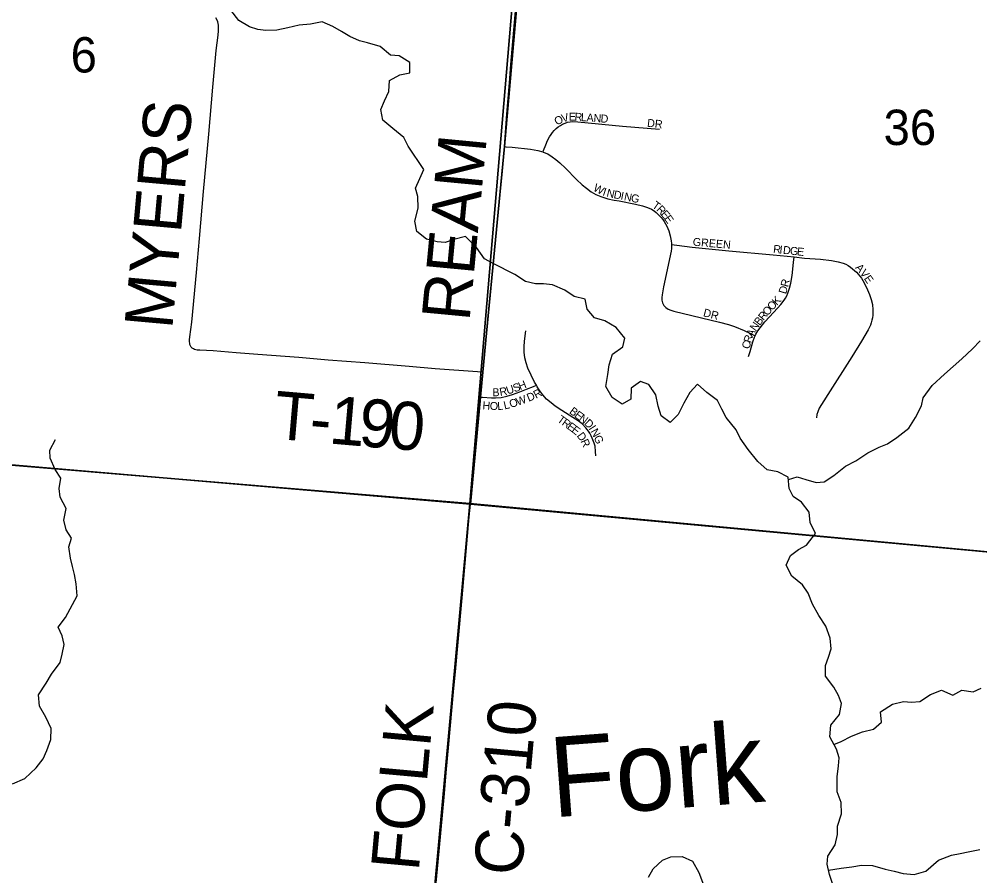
# Model space of a CAD drawing. Extents: x 1410790 to 1770854, y 566777 to 831614.
# Drawn here: x 1564816 to 1570818, y 709632 to 714986 of the extents above; entities that cross this region are included whole.
import ezdxf

# ---------------------------------------------------------------- set-up
doc = ezdxf.new("R2010")
doc.units = 0
for name, color, linetype in [('GM_X_County_Road', 7, 'Continuous'), ('GM_X_County_Road_Text', 7, 'Continuous'), ('GM_X_Minor_River', 7, 'Continuous'), ('GM_X_Minor_River_Text', 7, 'Continuous'), ('GM_X_Section', 7, 'Continuous'), ('GM_X_Section_Text', 7, 'Continuous'), ('GM_X_Township', 7, 'Continuous'), ('GM_X_Township_Road', 7, 'Continuous'), ('GM_X_Township_Road_Text', 7, 'Continuous'), ('GM_X_Township_Subdivision', 7, 'Continuous'), ('GM_X_Township_Subdivision_Text', 7, 'Continuous')]:
    doc.layers.add(name, color=color, linetype=linetype)

msp = doc.modelspace()

# ---------------------------------------------------------------- linework, layer by layer
at = {"layer": 'GM_X_County_Road'}
for points in [[(1567847.7, 714189.3), (1567863.9, 714392.9), (1567879.1, 714588.9), (1567888.8, 714703.3), (1567915.8, 715013.6), (1567937.6, 715258.5), (1567954, 715438.2), (1567971.6, 715634.2), (1567990.8, 715846.5), (1568008.1, 716042.5), (1568019.3, 716173.2), (1568035.4, 716352.9), (1568048.2, 716499.8), (1568060.7, 716646.9), (1568077.6, 716826.4), (1568091.6, 716973.3), (1568102.9, 717087.5), (1568116.8, 717250.8), (1568119.6, 717278.9)], [(1567744.9, 713110.3), (1567755.7, 713219.6), (1567769.2, 713366.2), (1567781.9, 713496.5), (1567791.5, 713594.4), (1567804.6, 713724.9), (1567835.3, 714034.1), (1567841.8, 714115.3), (1567847.7, 714189.3)], [(1567713.4, 712780.3), (1567736.3, 713023.8), (1567744.9, 713110.3)], [(1567699, 712623.5), (1567705.5, 712697.4), (1567713.4, 712780.3)], [(1567635.2, 711955.3), (1567671.1, 712328.1), (1567686.6, 712485.1), (1567699, 712623.5)], [(1567399.9, 709328.4), (1567405.5, 709411.7), (1567439.3, 709786.8), (1567473.1, 710145.6), (1567484.9, 710276.2), (1567501.2, 710455.7), (1567530.6, 710782), (1567544, 710928.8), (1567559.1, 711092), (1567583.2, 711369.5), (1567627.9, 711875.4), (1567635.1, 711954), (1567635.2, 711955.3)]]:
    msp.add_lwpolyline(points, dxfattribs=at)
at = {"layer": 'GM_X_Minor_River'}
for points in [[(1568475.7, 713100.2), (1568411.8, 713119.1), (1568364.3, 713173.8), (1568353.1, 713236.1), (1568283.1, 713253), (1568225.4, 713291.8), (1568147.6, 713324.8), (1568091.5, 713331.5), (1568041.4, 713332.1), (1567979.4, 713346.9), (1567913.7, 713389.8), (1567778.2, 713459.6), (1567724.4, 713488.3), (1567673.2, 713559.2), (1567605.8, 713628.2), (1567531.4, 713609), (1567477, 713589.6), (1567426.9, 713594.2), (1567361, 713611), (1567301.4, 713659.9), (1567288.2, 713724.3), (1567309.2, 713804.2), (1567306.1, 713878.5), (1567292.7, 713928.8), (1567319.6, 713990.7), (1567344.3, 714046.5), (1567245.9, 714192.1), (1567218.5, 714246.6), (1567151, 714301.6), (1567087.4, 714354.5), (1567076.2, 714420.8), (1567099, 714474.7), (1567125.8, 714534.5), (1567130.7, 714602.7), (1567195.3, 714638), (1567257.6, 714651.3), (1567256.4, 714715.5), (1567190.7, 714756.4), (1567136.6, 714761.1), (1567071.1, 714816), (1566993.2, 714839), (1566943.2, 714849.6), (1566881.4, 714878.5), (1566829.6, 714909.2), (1566775.8, 714939.9), (1566710, 714968.8), (1566635.7, 714955.6), (1566565.4, 714948.5), (1566495, 714931.3), (1566426.6, 714918), (1566356.4, 714914.9), (1566306.3, 714921.5), (1566254.4, 714938.2), (1566188.7, 714977.1), (1566139.3, 715041.8)], [(1569901.5, 709572.1), (1569878.3, 709640.6), (1569865.1, 709704.9), (1569869.7, 709755), (1569914.7, 709824.8), (1569929.6, 709890.8), (1569930.2, 709943), (1569953.3, 710018.9), (1569952.1, 710089.2), (1569926.9, 710157.7), (1569928.1, 710250), (1569935, 710320.2), (1569939.6, 710370.3), (1569922.2, 710422.7), (1569881.1, 710501.4), (1569888, 710573.5), (1569941, 710639.2), (1569953.9, 710709.2), (1569936.5, 710759.6), (1569907.1, 710810.1), (1569853.8, 710879), (1569854.6, 710947.2), (1569873.3, 710999.1), (1569890, 711051.1), (1569882.8, 711117.4), (1569855.7, 711191.9), (1569812.4, 711258.7), (1569773.2, 711329.4), (1569746, 711397.9), (1569710.5, 711450.5), (1569643, 711505.5), (1569607.8, 711574.1), (1569634.6, 711634), (1569685.2, 711671.5), (1569735.7, 711699), (1569792.8, 711770.5), (1569757.5, 711839.2), (1569752.4, 711905.5), (1569705, 711968.2), (1569653.3, 712002.9), (1569627.9, 712053.4), (1569620.7, 712123.7), (1569557, 712156.5), (1569488.9, 712169.4), (1569431.4, 712222.2), (1569370.2, 712297.2), (1569320.9, 712368), (1569295.5, 712418.5), (1569234.3, 712495.4), (1569206.9, 712547.9), (1569179.5, 712602.4), (1569111.9, 712653.3), (1569054.4, 712704.2), (1569007.6, 712652.6), (1568968.7, 712586.8), (1568933.7, 712515), (1568882.9, 712465.5), (1568827.3, 712506.3), (1568808, 712566.7), (1568794.8, 712637.1), (1568749.5, 712701.8), (1568697.6, 712720.5), (1568640.9, 712679), (1568638, 712610.8), (1568583.5, 712579.4), (1568521.9, 712622.2), (1568482.6, 712690.9), (1568493.6, 712765), (1568502.3, 712825.1), (1568523.3, 712893.1), (1568588, 712938.4), (1568600.7, 712992.4), (1568545.4, 713059.3), (1568475.7, 713100.2)], [(1569622.3, 712108), (1569676.9, 712125), (1569730.8, 712108.3), (1569796.8, 712089.5), (1569847, 712094.9), (1569905.7, 712134.4), (1569978.6, 712191.7), (1570043.2, 712225), (1570118, 712276.3), (1570188.7, 712311.6), (1570241.1, 712331), (1570299.7, 712370.4), (1570374.7, 712429.8), (1570417.6, 712497.4), (1570454.6, 712569.2), (1570465.3, 712619.3), (1570520.4, 712696.8), (1570597.5, 712766.2), (1570652.3, 712815.7), (1570707, 712863.2), (1570772, 712924.6), (1570820.8, 712976.2)], [(1564775.1, 710207.3), (1564851.7, 710240.5), (1564922.8, 710305.9), (1564965.6, 710363.5), (1564988.3, 710415.4), (1565013.2, 710483.3), (1565016.1, 710553.5), (1564982.9, 710624.2), (1564943.7, 710692.9), (1564936.5, 710763.2), (1564983.6, 710836.9), (1565018.4, 710892.6), (1565071.5, 710966.2), (1565084.2, 711018.2), (1565096.9, 711078.3), (1565083.6, 711132.6), (1565060.2, 711185.1), (1565105.1, 711246.7), (1565179, 711382.3), (1565171.9, 711456.6), (1565160.6, 711514.9), (1565149.2, 711565.2), (1565135.8, 711617.6), (1565126.7, 711687.9), (1565143.4, 711741.9), (1565110, 711794.4), (1565094.7, 711854.8), (1565109.6, 711926.9), (1565072.4, 711999.5), (1565065.1, 712051.8), (1565075.9, 712117.9), (1565040.5, 712170.5), (1565009.3, 712243.1), (1565007.9, 712293.2), (1565042.9, 712359)], [(1569907, 710451.9), (1569952.9, 710472.4), (1570017.5, 710505.8), (1570086.1, 710531.1), (1570154.5, 710548.3), (1570205.2, 710591.9), (1570197.9, 710656.2), (1570272.8, 710705.4), (1570341.2, 710720.7), (1570391.3, 710718.1), (1570443.5, 710721.5), (1570510.2, 710764.8), (1570578.7, 710792.1), (1570650.5, 710761.2), (1570707.1, 710792.6), (1570777.1, 710781.7), (1570827.6, 710805.2)], [(1569873, 709666.4), (1569953, 709679.8), (1570019.3, 709689), (1570079.6, 709698.4), (1570147.7, 709695.5), (1570227.7, 709674.5), (1570283.7, 709661.8), (1570339.7, 709647.1), (1570407.8, 709640.3), (1570482.2, 709661.5), (1570561.3, 709730.8), (1570641.9, 709761.9), (1570696.2, 709771.3), (1570746.5, 709782.8), (1570818.9, 709795.9)], [(1568748.9, 709623.9), (1568777.6, 709675.8), (1568836.5, 709729.2), (1568888.9, 709750.7), (1568959.1, 709751.8), (1569022.9, 709723), (1569062.1, 709652.3), (1569091.3, 709575.7)]]:
    msp.add_lwpolyline(points, dxfattribs=at)
at = {"layer": 'GM_X_Section'}
for points in [[(1562843.5, 717721.1), (1568082.8, 717254.1), (1567630.9, 711958.6), (1562327.3, 712402.7)], [(1568082.8, 717254.1), (1573281.6, 716755.8), (1572586.3, 711496.1), (1567630.9, 711958.6)], [(1562327.3, 712402.7), (1567630.9, 711958.6), (1567151.7, 706711.5), (1561825.1, 707214)], [(1567630.9, 711958.6), (1572586.3, 711496.1), (1572215, 706247.2), (1567151.7, 706711.5)]]:
    msp.add_lwpolyline(points, close=True, dxfattribs=at)
at = {"layer": 'GM_X_Township'}
for points in [[(1536109.9, 720210.8), (1535643.5, 714974.4), (1536009.5, 714944), (1541246.4, 714460.7), (1541691.9, 714420.1), (1541923.4, 714398.9), (1548437.3, 713818.3), (1549151.2, 713753.6), (1551760.4, 713504.3), (1552475.2, 713454.2), (1554274.2, 713261.1), (1561321.7, 712527.7), (1562336.2, 712409.9), (1567635.1, 711954), (1567699, 712623.5), (1567713.4, 712780.3), (1567736.3, 713023.8), (1567847.7, 714189.3), (1568119.6, 717279)], [(1568119.6, 717279), (1567847.7, 714189.3), (1567736.3, 713023.8), (1567713.4, 712780.3), (1567699, 712623.5), (1567635.1, 711954), (1572592.8, 711495.9), (1575739.3, 711217.4), (1577928.6, 711023.7), (1581827.8, 710704.5), (1586496.4, 710270.5)], [(1577928.6, 711023.7), (1575739.3, 711217.4), (1572592.8, 711495.9), (1567635.1, 711954), (1562336.2, 712409.9), (1561321.7, 712527.7), (1554274.2, 713261.1)]]:
    msp.add_lwpolyline(points, dxfattribs=at)
at = {"layer": 'GM_X_Township_Road'}
msp.add_lwpolyline([(1567713.4, 712780.3), (1567679.9, 712782.7), (1567415.5, 712800.9), (1567252.3, 712814.9), (1566974.8, 712837.5), (1566746.3, 712855.6), (1566564, 712870.6), (1566306.2, 712890.7), (1566171.3, 712901.2), (1566027.2, 712912.3), (1565945.5, 712916.9), (1565928.7, 712918), (1565920.3, 712919.4), (1565911.8, 712921.8), (1565904.6, 712925.2), (1565896.9, 712930.6), (1565891.4, 712936.5), (1565886.3, 712944.5), (1565883.2, 712952.2), (1565881.4, 712961.1), (1565880.6, 712969.4), (1565880.8, 712980.8), (1565882.7, 713000), (1565895.5, 713092), (1565924.5, 713402.1), (1565942.3, 713614.4), (1565968.1, 713908.2), (1566001.6, 714267.2), (1566017.9, 714463.2), (1566026, 714561.2), (1566036.3, 714675.3), (1566047.7, 714789.3), (1566058.5, 714886.9), (1566060.5, 714912.8), (1566060.9, 714935.7), (1566061.4, 714948.2), (1566060.2, 714957.9), (1566058.1, 714968.7), (1566053.8, 714980.5), (1566045.4, 714995)], dxfattribs=at)
at = {"layer": 'GM_X_Township_Subdivision'}
for points in [[(1568089.7, 714155.4), (1568093, 714164.7), (1568106, 714201.5), (1568117.5, 714228.2), (1568130.2, 714251), (1568139.1, 714264.8), (1568148.9, 714278), (1568159.8, 714290.3), (1568171.5, 714301.8), (1568184.1, 714312.4), (1568197.5, 714321.9), (1568211.7, 714330.1), (1568226.8, 714336.7), (1568242.5, 714341.5), (1568258.5, 714344.9), (1568274.9, 714346.1), (1568307.7, 714344.6), (1568585.8, 714317.9), (1568817.7, 714297.9)], [(1567847.7, 714189.3), (1567858.8, 714188.4), (1567897.1, 714185.4), (1568011.1, 714173.1), (1568056.2, 714165.5), (1568087.6, 714156.3), (1568089.7, 714155.4)], [(1568089.7, 714155.4), (1568118.3, 714143.3), (1568146.6, 714125.7), (1568169.2, 714108.7), (1568194.8, 714088.9), (1568230.7, 714055.7), (1568298.9, 713984.5), (1568334.7, 713950.1), (1568360.2, 713929), (1568389.2, 713906.8), (1568418.3, 713890.7), (1568450.4, 713878.5), (1568494.8, 713864), (1568534.7, 713855.4), (1568566, 713850.2), (1568667, 713830.3), (1568711.4, 713820.3), (1568742.7, 713809.6), (1568768, 713798.1), (1568784.1, 713788.2), (1568796.3, 713778.2), (1568815.6, 713758), (1568826.8, 713746.5), (1568837, 713734.1), (1568846.4, 713721.1), (1568862.4, 713693.1), (1568875.2, 713663.4), (1568884.7, 713632.6), (1568890.6, 713600.9), (1568892, 713584.8), (1568892.2, 713577.1)], [(1568892.2, 713577.1), (1568892.4, 713568.8), (1568891.6, 713552.7), (1568889.8, 713536.7), (1568842.5, 713312.1), (1568832.7, 713263.4), (1568830.9, 713246.6), (1568831.2, 713229), (1568835.5, 713212.3), (1568844.5, 713197.4), (1568856.8, 713184.6), (1568871.3, 713174.2), (1568888.9, 713166.8), (1568907.3, 713161.4), (1569191.1, 713091.9), (1569248.6, 713078), (1569285.3, 713065.7), (1569346.1, 713040.5), (1569390.4, 713019.6), (1569415.3, 713007.8)], [(1568892.2, 713577.1), (1568924.7, 713573.2), (1569022.1, 713561.4), (1569250.2, 713539), (1569527.3, 713512.8), (1569659.1, 713499.6)], [(1569415.3, 713007.8), (1569419.3, 713016.8), (1569432.3, 713037.4), (1569445.1, 713056.3), (1569475.7, 713094.1), (1569530.6, 713154.3), (1569575.1, 713202.5), (1569595.2, 713228.8), (1569604.1, 713242.8), (1569612.1, 713257.5), (1569619, 713272.6), (1569629.9, 713304), (1569637.7, 713336), (1569646, 713384.6), (1569655.3, 713465.7), (1569659.1, 713499.6)], [(1569659.1, 713499.6), (1569722.7, 713493.2), (1569823.3, 713485.1), (1569891.4, 713477.5), (1569934.3, 713469), (1569965.7, 713460.6), (1569981.7, 713454.5), (1569996.3, 713446.1), (1570010.8, 713436.1), (1570022.3, 713426), (1570047.1, 713404.5), (1570058.4, 713392.7), (1570068.9, 713380.2), (1570078.7, 713367), (1570095.6, 713339.1), (1570117.2, 713294.9), (1570130, 713264.8), (1570140.4, 713233.8), (1570147.3, 713201.8), (1570150.4, 713169.2), (1570150.5, 713152.8), (1570149.6, 713136.5), (1570147.6, 713120.3), (1570144.5, 713104.2), (1570140.1, 713088.5), (1570134.5, 713073.1), (1570120.7, 713043.4), (1570079.4, 712972.7), (1570018.6, 712875.6), (1569869.5, 712640.6), (1569844.8, 712601.2), (1569815.7, 712553.8), (1569805.7, 712530.8), (1569800.4, 712514.7), (1569798.4, 712493.8)], [(1568047.5, 712697.8), (1568036.5, 712717.9), (1568016.1, 712760.1), (1567995.1, 712804.8), (1567983.3, 712838.5), (1567975.7, 712869.6), (1567972.4, 712904.2), (1567971.5, 712937.8), (1567974.1, 712973.1), (1567981.7, 713038.8)], [(1569372.4, 712877), (1569383.3, 712909.6), (1569400.9, 712969.3), (1569410.8, 712997.6), (1569415.3, 713007.8)], [(1567699, 712623.5), (1567711.3, 712622.9), (1567766.9, 712619.8), (1567793, 712618.7), (1567826.7, 712621.2), (1567863.9, 712629.3), (1567898.2, 712639.7), (1567943.7, 712656.5), (1567985.8, 712673.4), (1568030.5, 712691.1), (1568047.5, 712697.8)], [(1568418.7, 712256.5), (1568418, 712283.5), (1568414.5, 712316.3), (1568408.8, 712336.5), (1568396.8, 712366.6), (1568389.4, 712381), (1568381.6, 712398), (1568372.4, 712411.5), (1568356.4, 712432.5), (1568332.8, 712456.1), (1568308.4, 712474.6), (1568276, 712495.4), (1568206.6, 712539.7), (1568165.8, 712567.8), (1568139.4, 712588.1), (1568111.3, 712611.1), (1568087.7, 712637.2), (1568068.4, 712663.3), (1568052.5, 712688.5), (1568047.5, 712697.8)]]:
    msp.add_lwpolyline(points, dxfattribs=at)

# ---------------------------------------------------------------- texts
at = {"layer": 'GM_X_County_Road_Text'}
for s, rotation, p in [('REAM', 84.58912, (1567629.1, 713092.4)), ('FOLK', 84.78199, (1567312.2, 709655.8)), ('C-310', 84.78233, (1567953.4, 709625.8))]:
    msp.add_text(s, height=300, rotation=rotation, dxfattribs=at).set_placement(p)
at = {"layer": 'GM_X_Minor_River_Text'}
msp.add_text('Fork', height=500, rotation=4.28297, dxfattribs=at).set_placement((1568150.1, 709996.6))
at = {"layer": 'GM_X_Section_Text'}
for s, p in [('6', (1565137.4, 714652.6)), ('36', (1570217.2, 714199.4))]:
    msp.add_text(s, height=221, rotation=0.00001, dxfattribs=at).set_placement(p)
at = {"layer": 'GM_X_Township_Road_Text'}
for s, rotation, p in [('MYERS', 84.85669, (1565772.2, 713043.9)), ('T', 355.031, (1566399.1, 712364.8)), ('1', 355.06433, (1566745.6, 712334.7)), ('9', 355.19294, (1566930.4, 712318.7)), ('0', 355.79117, (1567118, 712303)), ('-', 355.03939, (1566622.7, 712345.4))]:
    msp.add_text(s, height=300, rotation=rotation, dxfattribs=at).set_placement(p)
at = {"layer": 'GM_X_Township_Subdivision_Text'}
for s, rotation, p in [('V', 14.90044, (1568211.8, 714340.3)), ('E', 0.43716, (1568251, 714351.2)), ('R', 356.69487, (1568285.3, 714351.5)), ('L', 356.20046, (1568324.8, 714349.2)), ('A', 356.17284, (1568359.9, 714346.9)), ('N', 356.19817, (1568403.8, 714344)), ('D', 356.17284, (1568447.7, 714341)), ('O', 28.20749, (1568175.9, 714320.7)), ('DR', 353.66381, (1568737.6, 714314.1)), ('W', 332.54765, (1568398.7, 713915.9)), ('I', 342.38308, (1568458.2, 713885.9)), ('N', 346.85818, (1568483.2, 713878.2)), ('D', 348.54095, (1568527.6, 713867.8)), ('I', 348.65677, (1568570.9, 713859)), ('N', 348.66869, (1568592.5, 713854.7)), ('G', 348.69089, (1568635.6, 713846.1)), ('T', 325.02142, (1568767, 713811.7)), ('R', 314.81114, (1568794.1, 713793)), ('E', 310.41761, (1568821.3, 713765.7)), ('E', 304.82644, (1568843.3, 713739.9)), ('GREEN', 355.13323, (1569023.4, 713570.5)), ('R', 353.82069, (1569525.3, 713526.5)), ('I', 353.84998, (1569564.7, 713522.2)), ('D', 353.82395, (1569586.5, 713519.8)), ('G', 353.84199, (1569630.3, 713515.1)), ('E', 353.81367, (1569674, 713510.4)), ('A', 311.4121, (1570037.1, 713431.1)), ('V', 307.46867, (1570065.6, 713398.8)), ('E', 305.00098, (1570092.1, 713364.3)), ('D', 73.71531, (1569607.6, 713264.6)), ('R', 75.4127, (1569620.4, 713308.4)), ('K', 47.28814, (1569550.8, 713193.7)), ('O', 49.02174, (1569492.3, 713128.4)), ('O', 47.31902, (1569520.9, 713161.4)), ('DR', 345.2621, (1569086.6, 713130.2)), ('R', 50.03892, (1569467.1, 713098.3)), ('N', 54.28443, (1569417.6, 713032.1)), ('B', 52.02279, (1569443, 713067.4)), ('R', 72.79372, (1569388.2, 712958.7)), ('A', 63.59133, (1569399.2, 712994.5)), ('C', 75.71633, (1569378.6, 712921)), ('S', 19.32302, (1567910.8, 712653.5)), ('H', 21.9163, (1567946.3, 712666)), ('B', 0.85002, (1567773.2, 712628.9)), ('R', 10.30127, (1567821.7, 712630.4)), ('U', 18.28456, (1567868.1, 712639.4)), ('D', 22.07293, (1567999.6, 712594.3)), ('R', 27.65428, (1568045.2, 712613.1)), ('H', 355.62476, (1567709.5, 712547.6)), ('O', 358.50655, (1567756.1, 712544.1)), ('L', 3.58006, (1567804.9, 712543)), ('L', 12.99685, (1567849, 712546.5)), ('O', 17.59396, (1567887.5, 712555.6)), ('W', 19.52533, (1567931.1, 712569.5)), ('B', 323.23696, (1568249, 712526.2)), ('E', 323.26817, (1568280.8, 712502.4)), ('T', 324.33213, (1568174.1, 712473.8)), ('R', 324.32967, (1568202.7, 712453.3)), ('N', 323.23502, (1568309, 712481.4)), ('D', 316.17482, (1568343, 712456.1)), ('E', 324.059, (1568234.9, 712430.2)), ('E', 322.28316, (1568263, 712409.8)), ('I', 302.85343, (1568372.8, 712428)), ('N', 299.05886, (1568384.3, 712410.3)), ('D', 305.84258, (1568297.8, 712381.9)), ('R', 293.97975, (1568322.2, 712348.6)), ('G', 292.30881, (1568405, 712373.2))]:
    msp.add_text(s, height=50, rotation=rotation, dxfattribs=at).set_placement(p)

doc.saveas('drawing.dxf')
